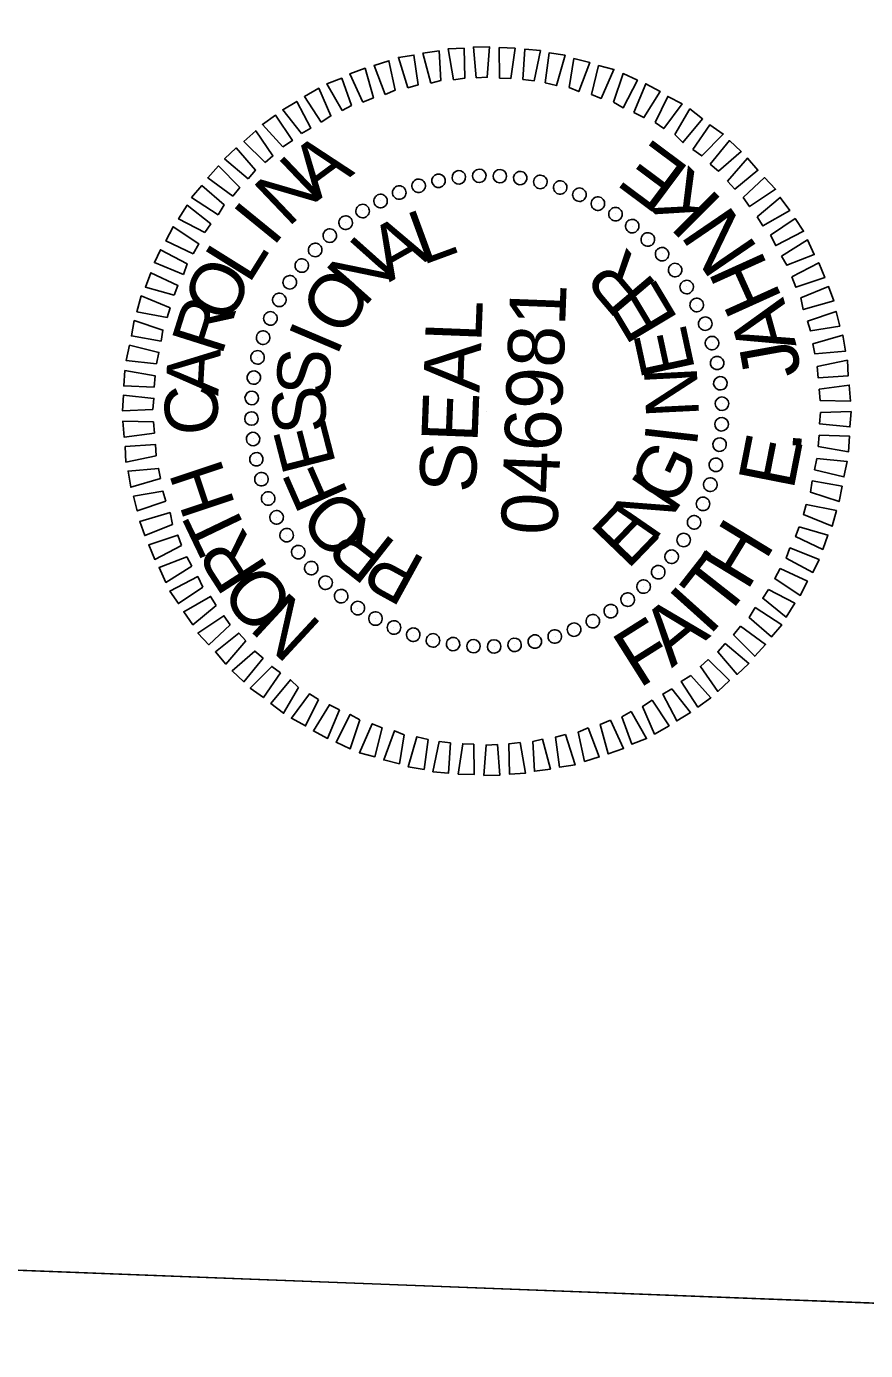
# Model space of a CAD drawing. Extents: x 2093420 to 2100301, y 676254 to 688367.
# Drawn here: x 2097263.7 to 2097353.1, y 687978 to 688119 of the extents above; entities that cross this region are included whole.
import ezdxf

# ---------------------------------------------------------------- set-up
doc = ezdxf.new("R2010")
doc.units = 0
for name, color, linetype in [('Old_Level_2', 7, 'Continuous'), ('Scratch_Level_2', 7, 'Continuous'), ('Sheet Layout Plan Border', 7, 'Continuous'), ('Sheet PE Seal Cell', 7, 'Continuous')]:
    doc.layers.add(name, color=color, linetype=linetype)

msp = doc.modelspace()

# ---------------------------------------------------------------- linework, layer by layer
at = {"layer": 'Old_Level_2'}
msp.add_lwpolyline([(2097250.84, 687986.99), (2097258.01, 688173.8), (2097369.31, 688169.53), (2097362.14, 687982.72)], close=True, dxfattribs=at)
msp.add_lwpolyline([(2097250.84, 687986.99), (2097258.01, 688173.8), (2097369.31, 688169.53), (2097362.14, 687982.72)], close=True, dxfattribs=at)
at = {"layer": 'Scratch_Level_2'}
msp.add_lwpolyline([(2098179.19, 686705.44), (2097129.59, 686735.95), (2097169.5, 687776.57), (2097177.9, 687989.79), (2097203.71, 687988.8), (2097408.56, 687980.94), (2097412.42, 688081.55), (2098157.98, 688052.95), (2098148.3, 687800.71), (2098221.09, 687797.91)], close=True, dxfattribs=at)
at = {"layer": 'Sheet Layout Plan Border'}
msp.add_lwpolyline([(2098179.19, 686705.44), (2097129.59, 686735.95), (2097169.5, 687776.57), (2097177.9, 687989.79), (2097203.71, 687988.8), (2097408.56, 687980.94), (2097412.42, 688081.55), (2098157.98, 688052.95), (2098148.3, 687800.71), (2098221.09, 687797.91)], close=True, dxfattribs=at)
at = {"layer": 'Sheet PE Seal Cell'}
for p, q in [((2097305.48, 688102.11), (2097305.48, 688102.11)), ((2097307.6, 688102.63), (2097307.6, 688102.63)), ((2097309.81, 688102.94), (2097309.81, 688102.94)), ((2097311.97, 688103.16), (2097311.97, 688103.16)), ((2097314.17, 688103.13), (2097314.17, 688103.13)), ((2097316.36, 688102.89), (2097316.36, 688102.89)), ((2097318.5, 688102.46), (2097318.5, 688102.46)), ((2097320.58, 688101.93), (2097320.58, 688101.93)), ((2097301.46, 688100.46), (2097301.46, 688100.46)), ((2097303.45, 688101.39), (2097303.45, 688101.39)), ((2097322.65, 688101.15), (2097322.65, 688101.15)), ((2097299.52, 688099.39), (2097299.52, 688099.39)), ((2097324.62, 688100.17), (2097324.62, 688100.17)), ((2097326.53, 688099.1), (2097326.53, 688099.1)), ((2097297.72, 688098.2), (2097297.72, 688098.2)), ((2097328.28, 688097.78), (2097328.28, 688097.78)), ((2097296.01, 688096.77), (2097296.01, 688096.77)), ((2097329.97, 688096.37), (2097329.97, 688096.37)), ((2097294.46, 688095.28), (2097294.46, 688095.28)), ((2097293.04, 688093.58), (2097293.04, 688093.58)), ((2097331.46, 688094.81), (2097331.46, 688094.81)), ((2097332.9, 688093.1), (2097332.9, 688093.1)), ((2097291.72, 688091.83), (2097291.72, 688091.83)), ((2097334.08, 688091.31), (2097334.08, 688091.31)), ((2097290.65, 688089.92), (2097290.65, 688089.92)), ((2097335.16, 688089.36), (2097335.16, 688089.36)), ((2097289.67, 688087.95), (2097289.67, 688087.95)), ((2097336.08, 688087.38), (2097336.08, 688087.38)), ((2097288.89, 688085.88), (2097288.89, 688085.88)), ((2097336.81, 688085.35), (2097336.81, 688085.35)), ((2097288.36, 688083.8), (2097288.36, 688083.8)), ((2097337.33, 688083.22), (2097337.33, 688083.22)), ((2097287.93, 688081.67), (2097287.93, 688081.67)), ((2097337.64, 688081.01), (2097337.64, 688081.01)), ((2097287.7, 688079.47), (2097287.7, 688079.47)), ((2097312.76, 688078.06), (2097312.76, 688078.06)), ((2097337.86, 688078.85), (2097337.86, 688078.85)), ((2097287.66, 688077.27), (2097287.66, 688077.27)), ((2097337.82, 688076.65), (2097337.82, 688076.65)), ((2097287.88, 688075.11), (2097287.88, 688075.11)), ((2097337.59, 688074.46), (2097337.59, 688074.46)), ((2097288.19, 688072.9), (2097288.19, 688072.9)), ((2097337.16, 688072.32), (2097337.16, 688072.32)), ((2097288.71, 688070.78), (2097288.71, 688070.78)), ((2097336.63, 688070.24), (2097336.63, 688070.24)), ((2097289.44, 688068.75), (2097289.44, 688068.75)), ((2097335.85, 688068.17), (2097335.85, 688068.17)), ((2097290.36, 688066.76), (2097290.36, 688066.76)), ((2097334.87, 688066.21), (2097334.87, 688066.21)), ((2097291.44, 688064.82), (2097291.44, 688064.82)), ((2097333.8, 688064.3), (2097333.8, 688064.3)), ((2097292.62, 688063.02), (2097292.62, 688063.02)), ((2097332.48, 688062.55), (2097332.48, 688062.55)), ((2097294.05, 688061.32), (2097294.05, 688061.32)), ((2097295.55, 688059.76), (2097295.55, 688059.76)), ((2097331.06, 688060.85), (2097331.06, 688060.85)), ((2097297.24, 688058.34), (2097297.24, 688058.34)), ((2097329.5, 688059.36), (2097329.5, 688059.36)), ((2097298.99, 688057.02), (2097298.99, 688057.02)), ((2097326, 688056.74), (2097326, 688056.74)), ((2097327.8, 688057.92), (2097327.8, 688057.92)), ((2097300.9, 688055.95), (2097300.9, 688055.95)), ((2097324.06, 688055.66), (2097324.06, 688055.66)), ((2097302.87, 688054.97), (2097302.87, 688054.97)), ((2097304.94, 688054.19), (2097304.94, 688054.19)), ((2097320.04, 688054.02), (2097320.04, 688054.02)), ((2097322.07, 688054.74), (2097322.07, 688054.74)), ((2097307.02, 688053.66), (2097307.02, 688053.66)), ((2097309.16, 688053.23), (2097309.16, 688053.23)), ((2097311.35, 688053), (2097311.35, 688053)), ((2097313.55, 688052.96), (2097313.55, 688052.96)), ((2097315.71, 688053.18), (2097315.71, 688053.18)), ((2097317.92, 688053.5), (2097317.92, 688053.5))]:
    msp.add_line(p, q, dxfattribs=at)
for points in [[(2097304.37, 688112.51), (2097303.35, 688115.75), (2097305.01, 688115.99), (2097305.44, 688112.82)], [(2097306.79, 688113.02), (2097305.97, 688116.2), (2097307.68, 688116.44), (2097307.86, 688113.28)], [(2097309.21, 688113.37), (2097308.64, 688116.65), (2097310.34, 688116.73), (2097310.42, 688113.53)], [(2097311.62, 688113.58), (2097311.34, 688116.85), (2097313.05, 688116.88), (2097312.82, 688113.64)], [(2097314.12, 688113.54), (2097314.09, 688116.79), (2097315.79, 688116.72), (2097315.32, 688113.49)], [(2097316.62, 688113.39), (2097316.84, 688116.63), (2097318.49, 688116.47), (2097317.81, 688113.24)], [(2097319, 688113.05), (2097319.43, 688116.24), (2097321.12, 688115.97), (2097320.19, 688112.75)], [(2097299.56, 688110.99), (2097298.18, 688114), (2097299.8, 688114.59), (2097300.68, 688111.45)], [(2097301.94, 688111.8), (2097300.76, 688114.9), (2097302.33, 688115.39), (2097303.01, 688112.26)], [(2097321.54, 688112.55), (2097322.06, 688115.63), (2097323.74, 688115.22), (2097322.57, 688112.11)], [(2097323.91, 688111.81), (2097324.68, 688114.88), (2097326.31, 688114.47), (2097324.94, 688111.37)], [(2097297.37, 688110.08), (2097295.73, 688112.94), (2097297.31, 688113.53), (2097298.35, 688110.64)], [(2097326.28, 688110.97), (2097327.3, 688114.03), (2097328.82, 688113.32), (2097327.31, 688110.38)], [(2097295.13, 688108.86), (2097293.33, 688111.58), (2097294.86, 688112.47), (2097296.15, 688109.52)], [(2097328.44, 688109.88), (2097329.71, 688112.94), (2097331.23, 688112.13), (2097329.52, 688109.34)], [(2097293.03, 688107.64), (2097291.02, 688110.17), (2097292.51, 688111.06), (2097294, 688108.2)], [(2097330.7, 688108.8), (2097332.06, 688111.6), (2097333.58, 688110.79), (2097331.63, 688108.16)], [(2097291.02, 688106.22), (2097288.86, 688108.6), (2097290.25, 688109.6), (2097292.05, 688106.88)], [(2097332.8, 688107.52), (2097334.41, 688110.26), (2097335.77, 688109.2), (2097333.67, 688106.68)], [(2097289.16, 688104.54), (2097286.89, 688106.78), (2097288.14, 688107.93), (2097289.98, 688105.26)], [(2097334.74, 688105.94), (2097336.55, 688108.57), (2097337.96, 688107.57), (2097335.67, 688105.25)], [(2097287.34, 688102.8), (2097284.82, 688104.95), (2097286.06, 688106.11), (2097288.12, 688103.73)], [(2097336.59, 688104.37), (2097338.63, 688106.89), (2097339.89, 688105.74), (2097337.46, 688103.63)], [(2097338.42, 688102.55), (2097340.56, 688105.02), (2097341.66, 688103.72), (2097339.19, 688101.72)], [(2097285.72, 688100.97), (2097283.04, 688102.92), (2097284.19, 688104.18), (2097286.45, 688101.89)], [(2097284.14, 688098.97), (2097281.31, 688100.83), (2097282.41, 688102.09), (2097284.78, 688100.05)], [(2097340.1, 688100.83), (2097342.38, 688102.95), (2097343.54, 688101.7), (2097340.77, 688099.86)], [(2097341.57, 688098.77), (2097344.05, 688100.83), (2097345.05, 688099.44), (2097342.19, 688097.8)], [(2097282.72, 688097.08), (2097279.92, 688098.54), (2097280.83, 688100), (2097283.35, 688098)], [(2097281.48, 688094.82), (2097278.58, 688096.19), (2097279.34, 688097.71), (2097282.07, 688095.9)], [(2097343, 688096.82), (2097345.62, 688098.57), (2097346.52, 688097.23), (2097343.56, 688095.7)], [(2097344.17, 688094.57), (2097346.93, 688096.32), (2097347.67, 688094.74), (2097344.73, 688093.6)], [(2097280.44, 688092.61), (2097277.34, 688093.88), (2097277.99, 688095.26), (2097280.84, 688093.75)], [(2097345.28, 688092.38), (2097348.14, 688093.87), (2097348.78, 688092.29), (2097345.69, 688091.26)], [(2097279.46, 688090.4), (2097276.39, 688091.27), (2097276.95, 688092.8), (2097279.85, 688091.43)], [(2097346.25, 688090.14), (2097349.19, 688091.33), (2097349.74, 688089.8), (2097346.5, 688088.88)], [(2097278.72, 688088.02), (2097275.49, 688088.65), (2097275.95, 688090.33), (2097279.01, 688089.06)], [(2097346.95, 688087.66), (2097349.99, 688088.69), (2097350.38, 688087.13), (2097347.26, 688086.6)], [(2097278.07, 688085.5), (2097274.89, 688086.07), (2097275.2, 688087.71), (2097278.26, 688086.69)], [(2097277.58, 688083.11), (2097274.34, 688083.44), (2097274.7, 688085.08), (2097277.82, 688084.31)], [(2097347.51, 688085.24), (2097350.7, 688086.16), (2097350.98, 688084.45), (2097347.72, 688084.18)], [(2097277.33, 688080.62), (2097274.08, 688080.75), (2097274.2, 688082.39), (2097277.43, 688081.82)], [(2097347.97, 688082.82), (2097351.2, 688083.49), (2097351.28, 688081.84), (2097348.07, 688081.61)], [(2097348.18, 688080.41), (2097351.39, 688080.83), (2097351.53, 688079.13), (2097348.28, 688079.2)], [(2097277.19, 688078.23), (2097273.93, 688078.1), (2097274.05, 688079.75), (2097277.29, 688079.42)], [(2097348.33, 688077.9), (2097351.59, 688078.02), (2097351.47, 688076.38), (2097348.23, 688076.7)], [(2097277.34, 688075.72), (2097274.12, 688075.29), (2097273.99, 688077), (2097277.24, 688076.92)], [(2097348.19, 688075.5), (2097351.43, 688075.38), (2097351.32, 688073.73), (2097348.09, 688074.31)], [(2097277.55, 688073.31), (2097274.32, 688072.63), (2097274.24, 688074.29), (2097277.45, 688074.51)], [(2097347.94, 688073.01), (2097351.18, 688072.69), (2097350.82, 688071.05), (2097347.7, 688071.82)], [(2097278.01, 688070.89), (2097274.82, 688069.96), (2097274.54, 688071.67), (2097277.8, 688071.95)], [(2097278.57, 688068.47), (2097275.52, 688067.43), (2097275.13, 688069), (2097278.26, 688069.53)], [(2097347.45, 688070.63), (2097350.63, 688070.06), (2097350.32, 688068.42), (2097347.25, 688069.43)], [(2097346.8, 688068.1), (2097350.03, 688067.48), (2097349.57, 688065.79), (2097346.51, 688067.06)], [(2097279.27, 688065.99), (2097276.32, 688064.8), (2097275.78, 688066.32), (2097279.02, 688067.25)], [(2097346.06, 688065.73), (2097349.13, 688064.86), (2097348.57, 688063.33), (2097345.67, 688064.69)], [(2097280.24, 688063.75), (2097277.38, 688062.26), (2097276.74, 688063.83), (2097279.83, 688064.86)], [(2097281.35, 688061.55), (2097278.58, 688059.81), (2097277.84, 688061.39), (2097280.79, 688062.53)], [(2097345.08, 688063.51), (2097348.18, 688062.24), (2097347.53, 688060.87), (2097344.68, 688062.38)], [(2097344.04, 688061.3), (2097346.94, 688059.94), (2097346.18, 688058.42), (2097343.45, 688060.22)], [(2097282.52, 688059.31), (2097279.9, 688057.56), (2097279, 688058.89), (2097281.96, 688060.43)], [(2097283.94, 688057.35), (2097281.46, 688055.3), (2097280.47, 688056.68), (2097283.33, 688058.33)], [(2097342.8, 688059.05), (2097345.6, 688057.59), (2097344.69, 688056.12), (2097342.17, 688058.12)], [(2097341.38, 688057.15), (2097344.21, 688055.29), (2097343.11, 688054.03), (2097340.74, 688056.07)], [(2097285.42, 688055.29), (2097283.13, 688053.18), (2097281.98, 688054.42), (2097284.75, 688056.27)], [(2097287.1, 688053.58), (2097284.96, 688051.11), (2097283.85, 688052.4), (2097286.33, 688054.41)], [(2097339.8, 688055.16), (2097342.48, 688053.21), (2097341.33, 688051.95), (2097339.07, 688054.24)], [(2097338.18, 688053.32), (2097340.7, 688051.17), (2097339.45, 688050.02), (2097337.39, 688052.4)], [(2097288.93, 688051.76), (2097286.89, 688049.23), (2097285.63, 688050.38), (2097288.06, 688052.49)], [(2097336.36, 688051.59), (2097338.63, 688049.35), (2097337.38, 688048.2), (2097335.53, 688050.87)], [(2097290.77, 688050.18), (2097288.97, 688047.55), (2097287.56, 688048.56), (2097289.85, 688050.87)], [(2097334.5, 688049.91), (2097336.66, 688047.52), (2097335.27, 688046.53), (2097333.47, 688049.25)], [(2097292.72, 688048.61), (2097291.11, 688045.87), (2097289.75, 688046.92), (2097291.85, 688049.44)], [(2097332.49, 688048.48), (2097334.49, 688045.96), (2097333.01, 688045.06), (2097331.52, 688047.92)], [(2097294.82, 688047.33), (2097293.46, 688044.53), (2097291.94, 688045.34), (2097293.89, 688047.96)], [(2097330.39, 688047.26), (2097332.19, 688044.54), (2097330.65, 688043.65), (2097329.37, 688046.6)], [(2097297.08, 688046.24), (2097295.81, 688043.19), (2097294.29, 688044), (2097296, 688046.78)], [(2097299.24, 688045.16), (2097298.22, 688042.09), (2097296.7, 688042.8), (2097298.21, 688045.75)], [(2097328.14, 688046.05), (2097329.79, 688043.18), (2097328.21, 688042.59), (2097327.17, 688045.49)], [(2097301.61, 688044.32), (2097300.84, 688041.24), (2097299.2, 688041.66), (2097300.57, 688044.76)], [(2097323.57, 688044.32), (2097324.76, 688041.23), (2097323.19, 688040.74), (2097322.51, 688043.86)], [(2097325.96, 688045.13), (2097327.34, 688042.13), (2097325.72, 688041.54), (2097324.84, 688044.68)], [(2097303.98, 688043.57), (2097303.46, 688040.49), (2097301.78, 688040.91), (2097302.95, 688044.01)], [(2097306.51, 688043.08), (2097306.09, 688039.89), (2097304.4, 688040.16), (2097305.32, 688043.37)], [(2097308.9, 688042.73), (2097308.68, 688039.49), (2097307.03, 688039.65), (2097307.71, 688042.88)], [(2097311.4, 688042.59), (2097311.42, 688039.34), (2097309.73, 688039.4), (2097310.2, 688042.63)], [(2097316.31, 688042.75), (2097316.88, 688039.48), (2097315.18, 688039.39), (2097315.1, 688042.6)], [(2097318.72, 688043.11), (2097319.55, 688039.92), (2097317.84, 688039.69), (2097317.66, 688042.85)], [(2097321.15, 688043.62), (2097322.17, 688040.37), (2097320.51, 688040.14), (2097320.08, 688043.31)], [(2097313.9, 688042.54), (2097314.17, 688039.28), (2097312.47, 688039.25), (2097312.7, 688042.49)]]:
    msp.add_lwpolyline(points, close=True, dxfattribs=at)
for centre, major_axis in [((2097307.63, 688102.61), (-0.147, 0.705)), ((2097309.79, 688102.97), (-0.085, 0.715)), ((2097311.97, 688103.13), (-0.023, 0.72)), ((2097314.16, 688103.1), (0.04, 0.719)), ((2097316.33, 688102.89), (0.103, 0.713)), ((2097303.44, 688101.35), (-0.267, 0.668)), ((2097305.51, 688102.07), (-0.208, 0.689)), ((2097318.48, 688102.48), (0.164, 0.701)), ((2097320.59, 688101.89), (0.225, 0.684)), ((2097322.64, 688101.12), (0.284, 0.662)), ((2097301.45, 688100.45), (-0.325, 0.643)), ((2097324.61, 688100.17), (0.34, 0.635)), ((2097299.54, 688099.38), (-0.379, 0.612)), ((2097326.49, 688099.05), (0.394, 0.602)), ((2097297.73, 688098.14), (-0.431, 0.576)), ((2097328.27, 688097.77), (0.445, 0.566)), ((2097296.04, 688096.76), (-0.48, 0.537)), ((2097329.93, 688096.35), (0.493, 0.525)), ((2097294.48, 688095.23), (-0.525, 0.493)), ((2097331.45, 688094.78), (0.537, 0.48)), ((2097293.05, 688093.57), (-0.566, 0.445)), ((2097332.84, 688093.09), (0.576, 0.431)), ((2097291.77, 688091.79), (-0.602, 0.394)), ((2097334.07, 688091.28), (0.612, 0.379)), ((2097290.66, 688089.91), (-0.635, 0.34)), ((2097335.14, 688089.37), (0.643, 0.325)), ((2097289.71, 688087.94), (-0.662, 0.284)), ((2097336.05, 688087.38), (0.668, 0.267)), ((2097288.93, 688085.89), (-0.684, 0.225)), ((2097336.77, 688085.31), (0.689, 0.208)), ((2097288.34, 688083.79), (-0.701, 0.164)), ((2097337.31, 688083.19), (0.705, 0.147)), ((2097287.94, 688081.64), (-0.713, 0.103)), ((2097337.66, 688081.03), (0.715, 0.085)), ((2097287.72, 688079.46), (-0.719, 0.04)), ((2097337.83, 688078.85), (0.72, 0.023)), ((2097287.69, 688077.27), (-0.72, -0.023)), ((2097337.8, 688076.66), (0.719, -0.04)), ((2097287.86, 688075.09), (-0.715, -0.085)), ((2097337.58, 688074.49), (0.713, -0.103)), ((2097288.21, 688072.93), (-0.705, -0.147)), ((2097337.18, 688072.34), (0.701, -0.164)), ((2097288.75, 688070.81), (-0.689, -0.208)), ((2097336.59, 688070.23), (0.684, -0.225)), ((2097289.47, 688068.75), (-0.668, -0.267)), ((2097335.81, 688068.18), (0.662, -0.284)), ((2097290.37, 688066.75), (-0.643, -0.325)), ((2097334.86, 688066.21), (0.635, -0.34)), ((2097291.44, 688064.85), (-0.612, -0.379)), ((2097292.68, 688063.04), (-0.576, -0.431)), ((2097333.75, 688064.33), (0.602, -0.394)), ((2097332.47, 688062.55), (0.566, -0.445)), ((2097294.06, 688061.34), (-0.537, -0.48)), ((2097331.04, 688060.9), (0.525, -0.493)), ((2097295.59, 688059.78), (-0.493, -0.525)), ((2097329.48, 688059.37), (0.48, -0.537)), ((2097297.25, 688058.35), (-0.445, -0.566)), ((2097327.78, 688057.98), (0.431, -0.576)), ((2097299.03, 688057.08), (-0.394, -0.602)), ((2097300.91, 688055.96), (-0.34, -0.635)), ((2097325.98, 688056.75), (0.379, -0.612)), ((2097302.88, 688055.01), (-0.284, -0.662)), ((2097322.07, 688054.78), (0.267, -0.668)), ((2097324.07, 688055.68), (0.325, -0.643)), ((2097304.93, 688054.24), (-0.225, -0.684)), ((2097307.03, 688053.64), (-0.164, -0.701)), ((2097309.18, 688053.24), (-0.103, -0.713)), ((2097315.73, 688053.16), (0.085, -0.715)), ((2097317.89, 688053.51), (0.147, -0.705)), ((2097320.01, 688054.05), (0.208, -0.689)), ((2097311.36, 688053.02), (-0.04, -0.719)), ((2097313.55, 688052.99), (0.023, -0.72))]:
    msp.add_ellipse(centre, major_axis=major_axis, ratio=0.999708, dxfattribs=at)

# ---------------------------------------------------------------- texts
for s, height, rotation, p in [('A', 5.8, 36.4208, (2097294.65, 688100.37)), ('E', 6.15, 143.2967, (2097334.56, 688103.85)), ('N', 5.81, 43.6226, (2097291.59, 688097.54)), ('K', 6.18, 135.0128, (2097338.04, 688100.44)), ('I', 5.8, 50.8238, (2097289.96, 688095.45)), ('L', 5.72, 20.2045, (2097305.9, 688093.59)), ('N', 6.17, 124.287, (2097341.77, 688095.34)), ('A', 5.77, 29.564, (2097302.38, 688091.77)), ('N', 5.81, 48.2803, (2097299.67, 688089.02)), ('L', 5.78, 58.0246, (2097287.41, 688091.49)), ('R', 5.81, 130.2851, (2097331.04, 688091.47)), ('H', 6.13, 114.303, (2097344.32, 688090.05)), ('O', 5.74, 65.2249, (2097285.39, 688087.17)), ('O', 5.78, 57.6372, (2097297.54, 688085.75)), ('046981', 5.998, 87.8037, (2097320.26, 688064.79)), ('E', 5.79, 120.9278, (2097333.25, 688087.83)), ('R', 5.69, 72.4248, (2097284.51, 688083.85)), ('SEAL', 5.998, 87.8037, (2097311.57, 688069.3)), ('A', 6.07, 105.4627, (2097345.79, 688085.06)), ('I', 5.73, 66.9933, (2097296.77, 688083.78)), ('E', 5.69, 102.2155, (2097334.99, 688082.46)), ('J', 6.04, 100.2049, (2097346.29, 688082)), ('A', 5.64, 86.824, (2097284.15, 688079.66)), ('S', 5.64, 85.7041, (2097295.9, 688079.51)), ('N', 5.64, 92.8601, (2097335.4, 688077.49)), ('C', 5.65, 94.0236, (2097284.3, 688075.7)), ('S', 5.65, 95.0593, (2097295.81, 688075.91)), ('E', 5.7, 104.4148, (2097296.73, 688072.42)), ('I', 5.64, 83.5049, (2097335.13, 688074.15)), ('E', 6.02, 78.8614, (2097345.43, 688069.53)), ('.', 6, 85.9707, (2097346.23, 688073.64)), ('G', 5.74, 64.7939, (2097332.98, 688067.68)), ('H', 5.72, 108.4232, (2097286.01, 688068.03)), ('F', 5.76, 113.7707, (2097298.11, 688069.17)), ('N', 5.79, 55.4377, (2097330.58, 688063.97)), ('O', 5.81, 132.4849, (2097300.93, 688065.76)), ('E', 5.81, 46.0806, (2097327.77, 688061.07)), ('T', 5.77, 115.6235, (2097287.53, 688064.72)), ('R', 5.79, 141.8433, (2097303.31, 688063.91)), ('R', 5.8, 122.8242, (2097289.6, 688061.24)), ('H', 6.14, 58.677, (2097340.48, 688058.78)), ('P', 5.74, 151.2026, (2097306.45, 688062.19)), ('T', 6.17, 51.8768, (2097338, 688055.63)), ('O', 5.81, 130.0254, (2097292.56, 688057.67)), ('N', 5.8, 137.2272, (2097295.37, 688055.26)), ('I', 6.18, 48.0749, (2097336.45, 688054.01)), ('A', 6.17, 39.2345, (2097332.48, 688050.65)), ('F', 6.15, 32.2179, (2097328.98, 688048.45))]:
    msp.add_text(s, height=height, rotation=rotation, dxfattribs=at).set_placement(p)

doc.saveas('drawing.dxf')
